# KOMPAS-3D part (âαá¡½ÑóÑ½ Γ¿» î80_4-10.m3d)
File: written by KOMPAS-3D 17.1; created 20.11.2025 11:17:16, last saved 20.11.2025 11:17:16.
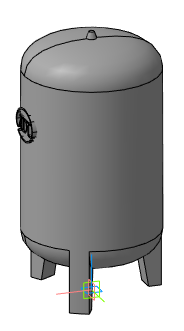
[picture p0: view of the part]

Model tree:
1. Операция без истории:5

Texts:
  REVIT MATERIAL OVERRIDDEN
  REVIT MATERIAL ID
  REVIT SUBCATEGORY ID
  REVIT CATEGORY ID
  REVIT ELEMENT ID
  REVIT BREP TAG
